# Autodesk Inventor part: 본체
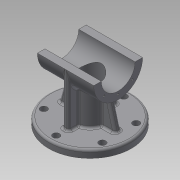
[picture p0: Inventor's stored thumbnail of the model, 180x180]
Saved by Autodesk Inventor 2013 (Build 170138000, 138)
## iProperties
Created: 2015-12
Part Number: 본체
Material: 알루미늄 6061
Document SubType Name: Modeling
Designer: mduedu
Density: 2.71 g/cm^3
Mass: 517.26 g
Surface Area: 494.064 cm^2
Volume: 190.871 cm^3
Author: mduedu
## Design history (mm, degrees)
sketch "스케치1"
  geometry: C1 r 55 at (0, 0); 1 further point
  constraints: 1 centre point, 1 coincident
  dimensions: "d124" = 110 diameter of C1
extrude "돌출1" new body sketch "스케치1" distance "d3" = 10; taper "d4" = 0 deg
sketch "스케치2"
  geometry: C1 r 32.5 at (80, 0); 1 further point
  constraints: 1 centre point, 1 horizontal alignment
  dimensions: "d5" = 65 diameter of C1; "d125" = 80 distance of C1.centre point (0, 0)
extrude "돌출2" join sketch "스케치2" stored distance "d7" = 75; taper "d8" = 0 deg
sketch "스케치3"
  geometry: C1 r 20 at (0, 0); 1 further point
  constraints: 1 centre point, 1 coincident
  dimensions: "d154" = 40 diameter of C1
extrude "돌출3" new body sketch "스케치3" stored distance "d12" = 75; taper "d13" = 0 deg
feature "결합1"
  node "솔리드2"
sketch "스케치19"
  geometry: L1 (0, 55)-(10, 55) reference; L2 (10, 55)-(10, 20) reference; L3 (10, 20)-(54.383, 20) reference; L4 (54.383, -20)-(10, -20) reference; L5 (10, -20)-(10, -55) reference; L6 (10, -55)-(0, -55) reference; L7 (0, -55)-(0, 55) reference; L8 (10, -32.5)-(80, -32.5); A1 r 32.5 centre (80, 0) between (54.383, -20) and (54.383, 20) reference; 1 further point
  constraints: 2 end point, 1 horizontal, 1 point on circle, 1 point on line, 1 tangent
feature "리브3" sketch "스케치19" dims "d161" = 1, "d162" = 8, "d163" = 0, "d164" = 0, "d165" = 1, "d166" = 1
sketch "스케치20"
  geometry: L1 (-37.5, 47.5)-(-37.5, 112.5) reference; L2 (-37.5, 112.5)-(37.5, 112.5) reference; L3 (37.5, 112.5)-(37.5, 47.5) reference; L4 (37.5, 47.5)-(20, 47.5) reference; L5 (20, 47.5)-(20, 10) reference; L6 (20, 10)-(55, 10) reference; L7 (55, 10)-(55, 0) reference; L8 (55, 0)-(-55, 0) reference; L9 (-55, 0)-(-55, 10) reference; L10 (-55, 10)-(-20, 10) reference; L11 (-20, 10)-(-20, 47.5) reference; L12 (-20, 47.5)-(-37.5, 47.5) reference; L13 (27.5, 47.5)-(37.548, 10); 1 further point
  constraints: 2 end point, 2 point on line
  dimensions: "d167" = 10 distance from line of L13.start L3; "d168" = 105 deg angle of L13 L6
feature "리브4" sketch "스케치20" dims "d169" = 1, "d170" = 8, "d171" = 0, "d172" = 0, "d173" = 1, "d174" = 1
fillet "모깎기14" dims "d175" = 3
fillet "모깎기15" dims "d176" = 3
fillet "모깎기7" dims "d41" = 3
hole "구멍2" diameter "d44" = 45; stored, may be unused: countersink angle "d48" = 90 deg, drill point angle "d50" = 118 deg; dims "d42" = 10, "d43" = 10, "d45" = 6, "d46" = 4, "d47" = 2, "d49" = 8
sketch "스케치7" dims "d52" = 26.5
  geometry: L1 (0, 0)-(32.5, 0); L2 (0, 0)-(0, 32.5); A1 r 32.5 centre (0, 0) between (32.5, 0) and (0, 32.5) reference; 3 further points
  constraints: 4 end point, 2 point on circle, 1 coincident, 1 horizontal, 1 point on line, 1 vertical alignment, 2 other
  dimensions: "d51" = 90 deg angle of L2 L1
hole "구멍3" sketch "스케치7" at (0, 26.5) diameter "d54" = 2.459; stored, may be unused: countersink angle "d58" = 90 deg, drill point angle "d60" = 118 deg; dims "d55" = 8, "d56" = 4, "d57" = 2, "d59" = 10
sketch "스케치9"
  geometry: L1 (-75, 82.5)-(75, 82.5); L2 (75, 82.5)-(75, 0); L3 (75, 0)-(-75, 0); L4 (-75, 0)-(-75, 82.5); C1 r 32.5 at (0, 0) reference; 2 further points
  constraints: 8 end point, 2 parallel, 1 coincident, 1 horizontal, 1 midpoint, 1 perpendicular
  dimensions: "d71" = 50 distance edge to line of C1 L1; "d116" = 150 distance between parallel lines of L2 L4
extrude "돌출5" cut sketch "스케치9" stored distance "d73" = 0; taper "d74" = 0 deg
node "작업 평면1"
sketch "스케치10"
  geometry: C1 r 15 at (0, 0); 1 further point
  constraints: 1 centre point, 1 coincident
  dimensions: "d156" = 30 diameter of C1
extrude "돌출6" cut sketch "스케치10" stored distance "d78" = 50; taper "d79" = 0 deg
sketch "스케치11"
  geometry: 2 further points
  constraints: 1 coincident
hole "구멍4" sketch "스케치11" at (0, 0) diameter "d81" = 12; stored, may be unused: countersink angle "d85" = 90 deg, drill point angle "d87" = 118 deg; dims "d82" = 8, "d83" = 30, "d84" = 10, "d86" = 10
sketch "스케치12"
  geometry: C1 r 10 at (0, 0); 1 further point
  constraints: 1 centre point, 1 coincident
  dimensions: "d88" = 20 diameter of C1
extrude "돌출7" cut sketch "스케치12" distance "d89" = 10; taper "d90" = 0 deg
chamfer "모따기1" distance "d91" = 1; stored, may be unused: second distance "d92" = 2, angle "d93" = 45 deg
sketch "스케치18" dims "d141" = 90
  geometry: C1 r 52 at (0, 0) reference; 2 further points
  constraints: 2 vertical alignment, 1 coincident, 2 other
hole "구멍8" sketch "스케치18" at (0, 45) diameter "d142" = 9; stored, may be unused: countersink angle "d146" = 90 deg, drill point angle "d148" = 118 deg; dims "d143" = 6, "d144" = 4, "d145" = 2, "d147" = 8
node "솔리드1"
mirror "대칭8"
mirror "대칭9"
pattern_circular "원형 패턴1" dims angle "d62" = 360 deg
mirror "대칭3"
pattern_circular "원형 패턴2" dims angle "d150" = 360 deg
node "절단 모서리 투영1"
node "절단 모서리 투영2"
